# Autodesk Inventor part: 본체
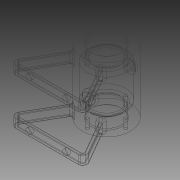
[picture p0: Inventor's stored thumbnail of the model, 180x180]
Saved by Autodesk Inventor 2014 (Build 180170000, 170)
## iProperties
Created: 2016-03
Part Number: 본체
Material: Generic
Document SubType Name: Modeling
Designer: user
Density: 1 g/cm^3
Appearance: Default
Author: user
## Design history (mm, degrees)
sketch "Sketch1"
  geometry: C1 r 26 at (0, 0); 1 further point
  constraints: 1 centre point, 1 coincident
  dimensions: "d0" = 52 diameter of C1
extrude "Extrusion1" new body sketch "Sketch1" stored distance "d1" = 70; taper "d2" = 0 deg
sketch "Sketch2"
  geometry: L1 (-26, -35)-(26, -35) reference; L2 (26, 35)-(-26, 35) reference; L3 (0, -35)-(18.15, -35); L4 (0, -21)-(21, -21); L5 (21, -21)-(21, 21); L6 (21, 21)-(0, 21); L7 (0, 21)-(0, -21); L8 (26, -35)-(-26, -35) reference; L9 (-26, -35)-(-26, 35) reference; L10 (-26, 35)-(26, 35) reference; L11 (26, 35)-(26, -35) reference; 2 further points
  constraints: 10 end point, 2 midpoint, 2 parallel, 1 coincident, 1 horizontal, 1 perpendicular, 1 point on line
  dimensions: "d3" = 21 distance between parallel lines of L7 L5; "d4" = 42 distance of L4.end L5.end
  node "Project Cut Edges1"
revolve "Revolution1" stored, may be unused: angle "d5" = 90 deg
sketch "Sketch3"
  geometry: C1 r 26 at (0, 0) reference
hole "Hole1" sketch "Sketch3" at (0, 0) diameter "d6" = 28; stored, may be unused: countersink angle "d10" = 90 deg, drill point angle "d12" = 0 deg; dims "d7" = 6, "d8" = 32, "d9" = 12, "d11" = 14
mirror "Mirror1"
sketch "Sketch4" dims "d13" = 42
  geometry: L1 (0, 0)-(0, 21); C1 r 26 at (0, 0) reference; 1 further point
  constraints: 2 end point, 1 coincident, 1 vertical, 1 vertical alignment, 3 other
hole "Hole2" sketch "Sketch4" at (0, 21) diameter "d14" = 3.242; stored, may be unused: countersink angle "d18" = 90 deg, drill point angle "d20" = 118 deg; dims "d15" = 8, "d16" = 32, "d17" = 12, "d19" = 10
pattern_circular "Circular Pattern1" dims angle "d22" = 360 deg
mirror "Mirror2"
chamfer "Chamfer1" distance "d24" = 1; stored, may be unused: second distance "d25" = 2, angle "d26" = 45 deg
fillet "Fillet1" dims "d27" = 0.3
fillet "Fillet2" dims "d28" = 3
workplane "Work Plane1"
sketch "Sketch5"
  geometry: C1 r 5 at (0, 0); 1 further point
  constraints: 1 centre point, 1 coincident
  dimensions: "d30" = 10 diameter of C1
extrude "Extrusion2" join sketch "Sketch5" stored distance "d31" = 70; taper "d32" = 0 deg
sketch "Sketch6"
  geometry: C1 r 5 at (0, 0) reference
hole "Hole3" sketch "Sketch6" at (0, 0) diameter "d33" = 5.188; stored, may be unused: countersink angle "d37" = 90 deg, drill point angle "d39" = 0 deg; dims "d34" = 8, "d35" = 32, "d36" = 12, "d38" = 10
fillet "Fillet3" dims "d40" = 2
sketch "Sketch7"
  geometry: L1 (0, 0)-(7.506, -28.012); L2 (-2.594, 29)-(-2.594, 20.839) reference; L3 (2.594, 20.839)-(2.594, 29) reference; L4 (2.594, 29)-(5, 29) reference; L5 (5, 29)-(5, 27.111) reference; L6 (-5, 27.111)-(-5, 29) reference; L7 (-5, 29)-(-2.594, 29) reference; L8 (0, 31.416)-(0, -33.389); L9 (7.506, -28.012)-(1.71, -29.565); L10 (1.71, -29.565)-(-0.587, -20.992); A1 r 21 centre (0, 0) between (-2.594, 20.839) and (2.594, 20.839) reference; A2 r 26 centre (0, 0) between (-6.5, 25.174) and (6.5, 25.174) reference; A3 r 21 centre (0, 0) between (-0.587, -20.992) and (5.435, -20.284)
  constraints: 10 end point, 3 point on circle, 2 perpendicular, 1 centre point, 1 coincident, 1 parallel, 1 point on line, 2 other
  dimensions: "d41" = 15 deg angle of L8 L1; "d42" = 29 distance of L1.end L1.start; "d75" = 12 diameter of L10 L1
revolve "Revolution2" sketch "Sketch7" stored, may be unused: angle "d43" = 90 deg
sketch "Sketch8"
  geometry: C1 r 6 at (0, 0) reference
revolve "Revolution3" stored, may be unused: angle "d44" = 90 deg
hole "Hole4" sketch "Sketch8" diameter "d45" = 5.188; stored, may be unused: countersink angle "d49" = 90 deg, drill point angle "d51" = 0 deg; dims "d46" = 8, "d47" = 32, "d48" = 12, "d50" = 10
fillet "Fillet4" dims "d52" = 2
workplane "Work Plane2"
sketch "Sketch9"
  geometry: L1 (-16.613, -20)-(-38.264, -57.5); L2 (-33.934, -65)-(0, -65); L3 (0, -67.231)-(0, 0); L4 (-14.183, -21.791)-(-35.666, -59); L5 (-33.934, -62)-(0, -62); L6 (16.613, -20)-(38.264, -57.5); L7 (33.934, -65)-(0, -65); L8 (14.183, -21.791)-(35.666, -59); L9 (33.934, -62)-(0, -62); A1 r 26 centre (0, 0) between (-16.613, -20) and (-14.183, -21.791) reference; A2 r 5 centre (-33.934, -60) between (-38.264, -57.5) and (-33.934, -65); A3 r 2 centre (-33.934, -60) between (-35.666, -59) and (-33.934, -62); A4 r 5 centre (33.934, -60) between (33.934, -65) and (38.264, -57.5); A5 r 2 centre (33.934, -60) between (33.934, -62) and (35.666, -59); A6 r 26 centre (0, 0) between (14.183, -21.791) and (16.613, -20); A7 r 26 centre (0, 0) between (-16.613, -20) and (-14.183, -21.791); 1 further point
  constraints: 18 end point, 14 point on circle, 7 symmetric about line, 6 centre point, 2 point on line, 2 tangent, 1 coincident, 1 horizontal, 1 vertical, 2 other
  dimensions: "d54" = 5 radius of A2; "d56" = 30 deg angle of L3 L1; "d57" = 45 distance from line of L2 L1.start; "d58" = 65 distance from line of L2 L3.end; "d59" = 3 distance between parallel lines of L4 L1
extrude "Extrusion3" join sketch "Sketch9" distance "d60" = 10; taper "d61" = 0 deg
mirror "Mirror3"
fillet "Fillet5" dims "d62" = 0.5
sketch "Sketch10"
  geometry: L1 (67.868, -9)-(0, -9) reference; L2 (67.868, -9)-(67.868, 0) reference; L3 (33.934, -29.5)-(33.934, 9.058); L4 (33.934, -4)-(13.934, -4); 2 further points
  constraints: 4 end point, 1 coincident, 1 parallel, 1 perpendicular, 1 point on line, 1 symmetric about line
  dimensions: "d63" = 20 distance of L4.start L4.end; "d64" = 5 distance between parallel lines of L4 L1
hole "Hole5" sketch "Sketch10" at (13.934, -4), (53.934, -4) diameter "d65" = 6; stored, may be unused: countersink angle "d69" = 90 deg, drill point angle "d71" = 0 deg; dims "d66" = 8, "d67" = 32, "d68" = 12, "d70" = 3
mirror "Mirror4"
workplane "Work Plane3"
fillet "Fillet6" dims "d73" = 3
fillet "Fillet7" dims "d76" = 3
body "Solid1"
node "Project Cut Edges2"
other parameters: "d29" = 29, "d72" = -26
